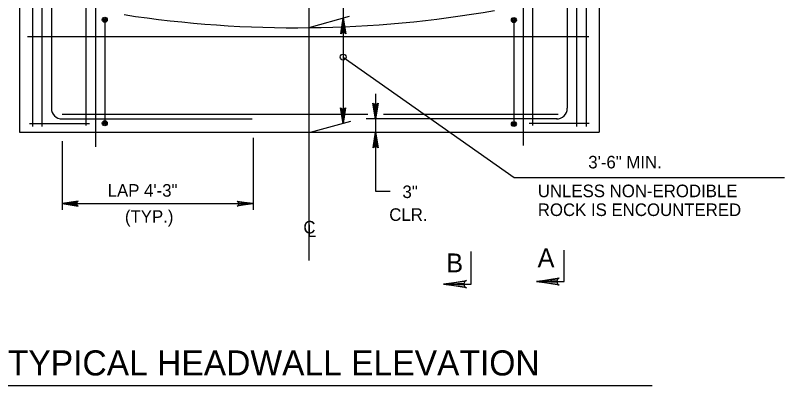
# Model space of a CAD drawing. Extents: x 639011 to 639866, y 298840 to 300028.
# Drawn here: x 639168.1 to 639351.9, y 299181.4 to 299269.9 of the extents above; entities that cross this region are included whole.
import ezdxf

# ---------------------------------------------------------------- set-up
doc = ezdxf.new("R2010")
doc.units = 0
doc.layers.add('2', color=7, linetype='Continuous')

msp = doc.modelspace()

# ---------------------------------------------------------------- linework, layer by layer
at = {"layer": '2'}
for p, q in [((639289.4, 299377.71), (639289.4, 299238.79)), ((639187.18, 299361.72), (639187.18, 299238.5)), ((639238.29, 299211.29), (639238.29, 299353.37)), ((639169.04, 299349.51), (639169.04, 299242.01)), ((639307.54, 299349.38), (639307.54, 299265.13)), ((639172.17, 299290.11), (639172.17, 299243.37)), ((639174.42, 299290.11), (639174.42, 299243.37)), ((639176.67, 299290.11), (639176.67, 299247.73)), ((639184.93, 299290.11), (639184.93, 299243.56)), ((639291.65, 299290.11), (639291.65, 299243.56)), ((639299.92, 299290.11), (639299.92, 299247.72)), ((639302.17, 299290.11), (639302.17, 299243.37)), ((639304.42, 299290.11), (639304.42, 299243.37)), ((639246.38, 299273.15), (639246.38, 299269.24)), ((639189.43, 299268.24), (639189.43, 299244.63)), ((639238.29, 299267.01), (639247.92, 299269.67)), ((639245.79, 299265.44), (639246.38, 299269.24)), ((639246.38, 299269.24), (639245.95, 299265.63)), ((639246.21, 299265.77), (639246.38, 299269.24)), ((639246.38, 299269.24), (639246.38, 299244.01)), ((639246.38, 299269.24), (639246.58, 299265.77)), ((639246.84, 299265.64), (639246.38, 299269.24)), ((639246.38, 299269.24), (639247.02, 299265.45)), ((639246.38, 299269.24), (639246.4, 299265.77)), ((639287.15, 299268.24), (639287.15, 299244.63)), ((639170.93, 299264.84), (639305.06, 299264.84)), ((639245.95, 299265.63), (639245.79, 299265.44)), ((639245.95, 299265.63), (639246.21, 299265.77)), ((639246.21, 299265.77), (639246.58, 299265.77)), ((639246.58, 299265.77), (639246.84, 299265.64)), ((639247.02, 299265.45), (639246.84, 299265.64)), ((639307.54, 299265.13), (639307.54, 299242.01)), ((639246.38, 299259.92), (639287.28, 299231.17)), ((639254.15, 299251.15), (639254.15, 299245.13)), ((639254.15, 299245.13), (639253.51, 299248.93)), ((639253.51, 299248.93), (639253.69, 299248.73)), ((639253.95, 299248.6), (639253.69, 299248.73)), ((639253.69, 299248.73), (639254.15, 299245.13)), ((639254.31, 299248.61), (639253.95, 299248.6)), ((639254.15, 299245.13), (639253.95, 299248.6)), ((639254.15, 299245.13), (639254.13, 299248.6)), ((639254.74, 299248.93), (639254.15, 299245.13)), ((639254.15, 299245.13), (639254.58, 299248.74)), ((639254.31, 299248.61), (639254.15, 299245.13)), ((639254.58, 299248.74), (639254.31, 299248.61)), ((639254.58, 299248.74), (639254.74, 299248.93)), ((639179.25, 299246.26), (639252.31, 299246.26)), ((639246.38, 299244.01), (639245.75, 299247.8)), ((639245.75, 299247.8), (639245.92, 299247.61)), ((639246.18, 299247.48), (639245.92, 299247.61)), ((639245.92, 299247.61), (639246.38, 299244.01)), ((639246.38, 299244.01), (639246.18, 299247.48)), ((639246.55, 299247.48), (639246.18, 299247.48)), ((639246.38, 299244.01), (639246.37, 299247.48)), ((639246.97, 299247.81), (639246.38, 299244.01)), ((639246.38, 299244.01), (639246.81, 299247.62)), ((639246.55, 299247.48), (639246.38, 299244.01)), ((639246.81, 299247.62), (639246.55, 299247.48)), ((639246.81, 299247.62), (639246.97, 299247.81)), ((639256.03, 299246.26), (639297.74, 299246.26)), ((639179.07, 299245.13), (639224.65, 299245.13)), ((639238.54, 299242.01), (639248.25, 299244.62)), ((639297.52, 299245.13), (639251.91, 299245.13)), ((639254.15, 299245.13), (639254.15, 299227.9)), ((639171.43, 299244.01), (639185.74, 299244.01)), ((639305.15, 299244.01), (639290.84, 299244.01)), ((639169.04, 299242.01), (639187.18, 299242.01)), ((639187.18, 299242.01), (639289.4, 299242.01)), ((639224.86, 299240.65), (639224.86, 299223.42)), ((639253.56, 299238.21), (639254.15, 299242.01)), ((639254.15, 299242.01), (639253.71, 299238.4)), ((639253.98, 299238.53), (639254.15, 299242.01)), ((639254.15, 299242.01), (639254.34, 299238.54)), ((639254.6, 299238.41), (639254.15, 299242.01)), ((639254.15, 299242.01), (639254.78, 299238.21)), ((639254.15, 299242.01), (639254.16, 299238.54)), ((639289.4, 299242.01), (639307.54, 299242.01)), ((639179.25, 299239.79), (639179.25, 299223.42)), ((639253.71, 299238.4), (639253.56, 299238.21)), ((639253.71, 299238.4), (639253.98, 299238.53)), ((639253.98, 299238.53), (639254.34, 299238.54)), ((639254.34, 299238.54), (639254.6, 299238.41)), ((639254.78, 299238.21), (639254.6, 299238.41)), ((639287.28, 299231.17), (639351.86, 299231.17)), ((639254.15, 299227.9), (639257.62, 299227.9)), ((639183.06, 299225.5), (639179.25, 299224.91)), ((639179.25, 299224.91), (639182.86, 299225.34)), ((639182.73, 299225.08), (639179.25, 299224.91)), ((639179.25, 299224.91), (639224.86, 299224.91)), ((639179.25, 299224.91), (639182.72, 299224.72)), ((639182.85, 299224.45), (639179.25, 299224.91)), ((639179.25, 299224.91), (639183.05, 299224.28)), ((639179.25, 299224.91), (639182.73, 299224.9)), ((639182.73, 299225.08), (639182.72, 299224.72)), ((639182.72, 299224.72), (639182.85, 299224.45)), ((639182.86, 299225.34), (639182.73, 299225.08)), ((639183.05, 299224.28), (639182.85, 299224.45)), ((639182.86, 299225.34), (639183.06, 299225.5)), ((639221.25, 299225.34), (639221.06, 299225.5)), ((639221.06, 299225.5), (639224.86, 299224.91)), ((639224.86, 299224.91), (639221.06, 299224.28)), ((639221.06, 299224.28), (639221.26, 299224.45)), ((639221.25, 299225.34), (639221.38, 299225.08)), ((639224.86, 299224.91), (639221.25, 299225.34)), ((639221.26, 299224.45), (639224.86, 299224.91)), ((639221.39, 299224.72), (639221.26, 299224.45)), ((639221.38, 299225.08), (639224.86, 299224.91)), ((639221.38, 299225.08), (639221.39, 299224.72)), ((639224.86, 299224.91), (639221.39, 299224.72)), ((639224.86, 299224.91), (639221.39, 299224.9)), ((639276.96, 299205.64), (639276.96, 299213.47)), ((639299.21, 299206.27), (639299.21, 299213.77)), ((639292.59, 299206.27), (639299.21, 299206.27)), ((639292.59, 299206.27), (639299.21, 299206.27)), ((639270.34, 299205.64), (639276.96, 299205.64)), ((639270.34, 299205.64), (639276.96, 299205.64)), ((639164.88, 299181.42), (639320.19, 299181.42))]:
    msp.add_line(p, q, dxfattribs=at)
for points in [[(639275.46, 299205.02), (639275.34, 299205.39), (639270.34, 299205.64), (639275.46, 299205.02), (639275.84, 299204.77), (639270.34, 299205.64), (639275.34, 299205.89), (639275.46, 299206.27), (639270.34, 299205.64), (639275.84, 299206.52), (639275.46, 299206.27)], [(639275.46, 299205.02), (639275.34, 299205.39), (639270.34, 299205.64), (639275.46, 299205.02), (639275.84, 299204.77), (639270.34, 299205.64), (639275.34, 299205.89), (639275.46, 299206.27), (639270.34, 299205.64), (639275.84, 299206.52), (639275.46, 299206.27)], [(639297.71, 299205.64), (639297.59, 299206.02), (639292.59, 299206.27), (639297.71, 299205.64), (639297.96, 299205.39), (639292.59, 299206.27), (639297.59, 299206.52), (639297.71, 299206.89), (639292.59, 299206.27), (639297.96, 299207.14), (639297.71, 299206.89)], [(639297.71, 299205.64), (639297.59, 299206.02), (639292.59, 299206.27), (639297.71, 299205.64), (639297.96, 299205.39), (639292.59, 299206.27), (639297.59, 299206.52), (639297.71, 299206.89), (639292.59, 299206.27), (639297.96, 299207.14), (639297.71, 299206.89)]]:
    msp.add_lwpolyline(points, dxfattribs=at)
for centre, radius in [((639189.43, 299268.84), 0.596), ((639189.43, 299268.84), 0.425), ((639189.43, 299268.84), 0.425), ((639189.43, 299268.84), 0.233), ((639189.43, 299268.84), 0.233), ((639189.43, 299268.84), 0.117), ((639189.43, 299268.84), 0.117), ((639189.43, 299268.84), 0.0503), ((639189.43, 299268.84), 0.0503), ((639287.17, 299268.76), 0.596), ((639287.17, 299268.76), 0.425), ((639287.17, 299268.76), 0.425), ((639287.17, 299268.76), 0.233), ((639287.17, 299268.76), 0.233), ((639287.17, 299268.76), 0.117), ((639287.17, 299268.76), 0.117), ((639287.17, 299268.76), 0.0503), ((639287.17, 299268.76), 0.0503), ((639246.38, 299259.92), 0.706), ((639189.43, 299244.1), 0.596), ((639189.43, 299244.1), 0.425), ((639189.43, 299244.1), 0.425), ((639189.43, 299244.1), 0.233), ((639189.43, 299244.1), 0.233), ((639287.17, 299243.93), 0.596), ((639287.17, 299243.93), 0.425), ((639287.17, 299243.93), 0.425), ((639189.43, 299244.1), 0.117), ((639189.43, 299244.1), 0.117), ((639189.43, 299244.1), 0.0503), ((639189.43, 299244.1), 0.0503), ((639287.17, 299243.93), 0.233), ((639287.17, 299243.93), 0.233), ((639287.17, 299243.93), 0.117), ((639287.17, 299243.93), 0.117), ((639287.17, 299243.93), 0.0503), ((639287.17, 299243.93), 0.0503)]:
    msp.add_circle(centre, radius, dxfattribs=at)
for centre, radius, start, end in [((639235.19, 299539.88), 272.95, 261.3243, 279.9929), ((639179.25, 299247.71), 2.58, 180, 270), ((639297.34, 299247.71), 2.58, 270, 0)]:
    msp.add_arc(centre, radius, start, end, dxfattribs=at)

# ---------------------------------------------------------------- texts
for s, height, p in [('3\'-6" MIN.', 3, (639304.95, 299233.32)), ('LAP 4\'-3"', 3, (639190.12, 299226.56)), ('3"', 3, (639260.55, 299226.23)), ('UNLESS NON-ERODIBLE', 3, (639292.89, 299226.44)), ('ROCK IS ENCOUNTERED', 3, (639292.89, 299221.94)), ('(TYP.)', 3, (639194.24, 299220.33)), ('CLR.', 3, (639257.4, 299220.78)), ('C', 3, (639236.87, 299217.77)), ('L', 3, (639237.74, 299216.9)), ('A', 4.5, (639292.85, 299209.71)), ('B', 4.5, (639271.02, 299208.49)), ('TYPICAL HEADWALL ELEVATION', 6, (639166.26, 299183.84))]:
    msp.add_text(s, height=height, dxfattribs=at).set_placement(p)

doc.saveas('drawing.dxf')
